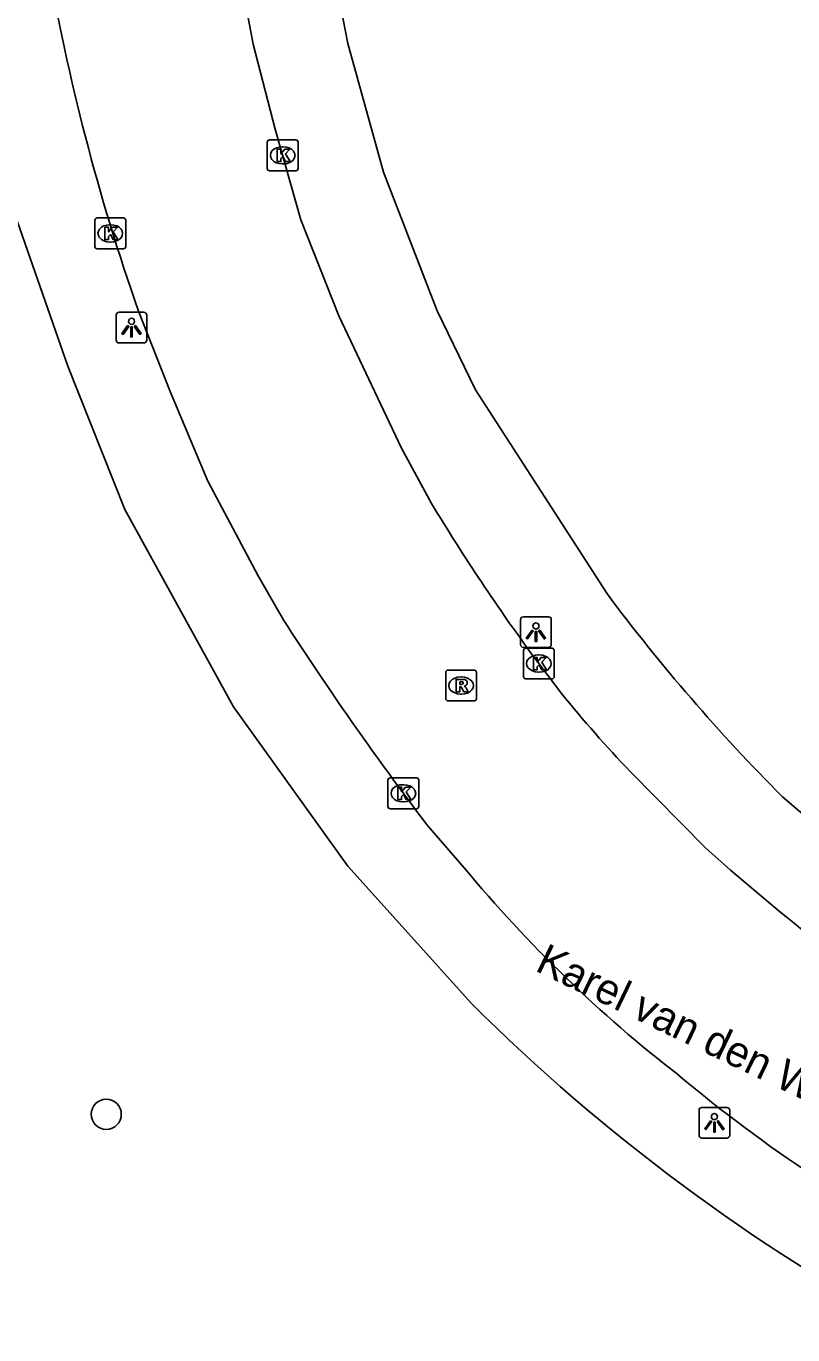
# Model space of a CAD drawing. Extents: x 161141 to 161601, y 381708 to 382245.
# Drawn here: x 161258.19 to 161283.09, y 381879.7 to 381922.19 of the extents above; entities that cross this region are included whole.
import ezdxf

# ---------------------------------------------------------------- set-up
doc = ezdxf.new("R2010")
doc.units = 0
for name, color, linetype in [('IMGEO_Boom', 7, 'Continuous'), ('IMGEO_Kolk', 7, 'Continuous'), ('IMGEO_Lichtpunt', 7, 'Continuous'), ('IMGEO_Openbare_ruimte_label', 7, 'Continuous'), ('IMGEO_Rijbaan_lokaal_open', 7, 'Continuous'), ('IMGEO_Rioolput', 7, 'Continuous'), ('IMGEO_Voetpad_open', 7, 'Continuous')]:
    doc.layers.add(name, color=color, linetype=linetype)

msp = doc.modelspace()

# ---------------------------------------------------------------- linework, layer by layer
at = {"layer": 'IMGEO_Boom'}
msp.add_circle((161260.788, 381886.858), 0.489, dxfattribs=at)
at = {"layer": 'IMGEO_Kolk'}
for p, q in [((161266.018, 381917.569), (161266.018, 381918.421)), ((161266.093, 381918.495), (161266.945, 381918.495)), ((161267.019, 381918.421), (161267.019, 381917.569)), ((161266.506, 381918.275), (161266.531, 381918.275)), ((161266.529, 381917.715), (161266.504, 381917.715)), ((161266.945, 381917.495), (161266.093, 381917.495)), ((161260.418, 381915.035), (161260.418, 381915.887)), ((161260.493, 381915.961), (161261.345, 381915.961)), ((161261.419, 381915.887), (161261.419, 381915.035)), ((161260.906, 381915.741), (161260.931, 381915.741)), ((161260.929, 381915.181), (161260.904, 381915.181)), ((161261.345, 381914.961), (161260.493, 381914.961)), ((161274.34, 381901.067), (161274.34, 381901.919)), ((161274.415, 381901.993), (161275.267, 381901.993)), ((161275.341, 381901.919), (161275.341, 381901.067)), ((161274.828, 381901.773), (161274.853, 381901.773)), ((161274.851, 381901.213), (161274.826, 381901.213)), ((161275.267, 381900.993), (161274.415, 381900.993)), ((161269.938, 381896.854), (161269.938, 381897.706)), ((161270.013, 381897.78), (161270.865, 381897.78)), ((161270.939, 381897.706), (161270.939, 381896.854)), ((161270.426, 381897.56), (161270.451, 381897.56)), ((161270.865, 381896.78), (161270.013, 381896.78)), ((161270.449, 381897), (161270.424, 381897))]:
    msp.add_line(p, q, dxfattribs=at)
for points in [[(161266.018, 381917.569), (161266.018, 381918.421)], [(161266.093, 381918.495), (161266.945, 381918.495)], [(161267.019, 381918.421), (161267.019, 381917.569)], [(161266.339, 381918.195), (161266.462, 381918.195), (161266.462, 381918.044), (161266.592, 381918.195), (161266.756, 381918.195), (161266.61, 381918.044), (161266.763, 381917.795), (161266.611, 381917.795), (161266.526, 381917.959), (161266.462, 381917.892), (161266.462, 381917.795), (161266.339, 381917.795), (161266.339, 381918.195)], [(161266.945, 381917.495), (161266.093, 381917.495)], [(161260.418, 381915.035), (161260.418, 381915.887)], [(161260.493, 381915.961), (161261.345, 381915.961)], [(161261.419, 381915.887), (161261.419, 381915.035)], [(161260.739, 381915.661), (161260.862, 381915.661), (161260.862, 381915.51), (161260.992, 381915.661), (161261.156, 381915.661), (161261.01, 381915.51), (161261.163, 381915.261), (161261.011, 381915.261), (161260.926, 381915.425), (161260.862, 381915.358), (161260.862, 381915.261), (161260.739, 381915.261), (161260.739, 381915.661)], [(161261.345, 381914.961), (161260.493, 381914.961)], [(161274.34, 381901.067), (161274.34, 381901.919)], [(161274.415, 381901.993), (161275.267, 381901.993)], [(161275.341, 381901.919), (161275.341, 381901.067)], [(161274.661, 381901.693), (161274.784, 381901.693), (161274.784, 381901.542), (161274.914, 381901.693), (161275.078, 381901.693), (161274.932, 381901.542), (161275.085, 381901.293), (161274.933, 381901.293), (161274.848, 381901.457), (161274.784, 381901.39), (161274.784, 381901.293), (161274.661, 381901.293), (161274.661, 381901.693)], [(161275.267, 381900.993), (161274.415, 381900.993)], [(161269.938, 381896.854), (161269.938, 381897.706)], [(161270.013, 381897.78), (161270.865, 381897.78)], [(161270.939, 381897.706), (161270.939, 381896.854)], [(161270.259, 381897.48), (161270.382, 381897.48), (161270.382, 381897.329), (161270.512, 381897.48), (161270.676, 381897.48), (161270.53, 381897.329), (161270.683, 381897.08), (161270.531, 381897.08), (161270.446, 381897.244), (161270.382, 381897.177), (161270.382, 381897.08), (161270.259, 381897.08), (161270.259, 381897.48)], [(161270.865, 381896.78), (161270.013, 381896.78)]]:
    msp.add_lwpolyline(points, dxfattribs=at)
for centre, start, end in [((161266.095, 381918.419), 91.552, 178.448), ((161266.095, 381918.419), 91.552, 178.448), ((161266.943, 381918.419), 1.552, 88.448), ((161266.943, 381918.419), 1.552, 88.448), ((161266.095, 381917.571), 181.552, 268.448), ((161266.095, 381917.571), 181.552, 268.448), ((161266.943, 381917.571), 271.552, 358.448), ((161266.943, 381917.571), 271.552, 358.448), ((161260.495, 381915.885), 91.552, 178.448), ((161260.495, 381915.885), 91.552, 178.448), ((161261.343, 381915.885), 1.552, 88.448), ((161261.343, 381915.885), 1.552, 88.448), ((161260.495, 381915.037), 181.552, 268.448), ((161260.495, 381915.037), 181.552, 268.448), ((161261.343, 381915.037), 271.552, 358.448), ((161261.343, 381915.037), 271.552, 358.448), ((161274.417, 381901.917), 91.552, 178.448), ((161274.417, 381901.917), 91.552, 178.448), ((161275.265, 381901.917), 1.552, 88.448), ((161275.265, 381901.917), 1.552, 88.448), ((161274.417, 381901.069), 181.552, 268.448), ((161274.417, 381901.069), 181.552, 268.448), ((161275.265, 381901.069), 271.552, 358.448), ((161275.265, 381901.069), 271.552, 358.448), ((161270.015, 381897.704), 91.552, 178.448), ((161270.015, 381897.704), 91.552, 178.448), ((161270.863, 381897.704), 1.552, 88.448), ((161270.863, 381897.704), 1.552, 88.448), ((161270.015, 381896.856), 181.552, 268.448), ((161270.015, 381896.856), 181.552, 268.448), ((161270.863, 381896.856), 271.552, 358.448), ((161270.863, 381896.856), 271.552, 358.448)]:
    msp.add_arc(centre, 0.0765, start, end, dxfattribs=at)
for centre, major_axis, ratio, start_param, end_param in [((161266.505, 381917.995), (-0.387, 0.002), 0.722429, 4.712389, 7.853982), ((161266.53, 381917.995), (-0.39, 0.002), 0.717154, 1.570796, 4.712389), ((161260.905, 381915.461), (-0.387, 0.002), 0.722429, 4.712389, 7.853982), ((161260.93, 381915.461), (-0.39, 0.002), 0.717154, 1.570796, 4.712389), ((161274.827, 381901.493), (-0.387, 0.002), 0.722429, 4.712389, 7.853982), ((161274.852, 381901.493), (-0.39, 0.002), 0.717154, 1.570796, 4.712389), ((161270.425, 381897.28), (-0.387, 0.002), 0.722429, 4.712389, 7.853982), ((161270.45, 381897.28), (-0.39, 0.002), 0.717154, 1.570796, 4.712389)]:
    msp.add_ellipse(centre, major_axis=major_axis, ratio=ratio, start_param=start_param, end_param=end_param, dxfattribs=at)
at = {"layer": 'IMGEO_Lichtpunt'}
for p, q in [((161262.011, 381912.901), (161261.203, 381912.901)), ((161262.011, 381912.901), (161261.203, 381912.901)), ((161261.109, 381912.806), (161261.109, 381911.999)), ((161261.109, 381912.806), (161261.109, 381911.999)), ((161262.105, 381911.999), (161262.105, 381912.806)), ((161262.105, 381911.999), (161262.105, 381912.806)), ((161261.203, 381911.905), (161262.011, 381911.905)), ((161261.203, 381911.905), (161262.011, 381911.905)), ((161274.246, 381902.917), (161274.246, 381902.11)), ((161274.246, 381902.917), (161274.246, 381902.11)), ((161275.148, 381903.012), (161274.34, 381903.012)), ((161275.148, 381903.012), (161274.34, 381903.012)), ((161275.242, 381902.11), (161275.242, 381902.917)), ((161275.242, 381902.11), (161275.242, 381902.917)), ((161274.34, 381902.016), (161275.148, 381902.016)), ((161274.34, 381902.016), (161275.148, 381902.016)), ((161280.043, 381886.985), (161280.043, 381886.178)), ((161280.043, 381886.985), (161280.043, 381886.178)), ((161280.945, 381887.08), (161280.137, 381887.08)), ((161280.945, 381887.08), (161280.137, 381887.08)), ((161281.039, 381886.178), (161281.039, 381886.985)), ((161281.039, 381886.178), (161281.039, 381886.985)), ((161280.137, 381886.084), (161280.945, 381886.084)), ((161280.137, 381886.084), (161280.945, 381886.084))]:
    msp.add_line(p, q, dxfattribs=at)
for points in [[(161261.483, 381912.47), (161261.522, 381912.442), (161261.334, 381912.18), (161261.296, 381912.207), (161261.483, 381912.47)], [(161261.585, 381912.422), (161261.632, 381912.422), (161261.632, 381912.1), (161261.585, 381912.1), (161261.585, 381912.422)], [(161261.695, 381912.442), (161261.733, 381912.469), (161261.92, 381912.207), (161261.881, 381912.179), (161261.695, 381912.442)], [(161274.62, 381902.581), (161274.659, 381902.553), (161274.471, 381902.291), (161274.433, 381902.318), (161274.62, 381902.581)], [(161274.722, 381902.533), (161274.769, 381902.533), (161274.769, 381902.211), (161274.722, 381902.211), (161274.722, 381902.533)], [(161274.832, 381902.553), (161274.87, 381902.58), (161275.057, 381902.318), (161275.018, 381902.29), (161274.832, 381902.553)], [(161280.417, 381886.649), (161280.456, 381886.621), (161280.268, 381886.359), (161280.23, 381886.386), (161280.417, 381886.649)], [(161280.519, 381886.601), (161280.566, 381886.601), (161280.566, 381886.279), (161280.519, 381886.279), (161280.519, 381886.601)], [(161280.629, 381886.621), (161280.667, 381886.648), (161280.854, 381886.386), (161280.815, 381886.358), (161280.629, 381886.621)]]:
    msp.add_lwpolyline(points, dxfattribs=at)
for centre in [(161261.608, 381912.604), (161274.745, 381902.715), (161280.542, 381886.783)]:
    msp.add_circle(centre, 0.0994, dxfattribs=at)
for centre, start, end in [((161261.203, 381912.806), 90, 180), ((161261.203, 381912.806), 90, 180), ((161262.011, 381912.806), 0, 90), ((161262.011, 381912.806), 0, 90), ((161261.203, 381911.999), 180, 270), ((161261.203, 381911.999), 180, 270), ((161262.011, 381911.999), 270, 0), ((161262.011, 381911.999), 270, 360), ((161274.34, 381902.917), 90, 180), ((161274.34, 381902.917), 90, 180), ((161275.148, 381902.917), 0, 90), ((161275.148, 381902.917), 0, 90), ((161274.34, 381902.11), 180, 270), ((161274.34, 381902.11), 180, 270), ((161275.148, 381902.11), 270, 0), ((161275.148, 381902.11), 270, 360), ((161280.137, 381886.985), 90, 180), ((161280.137, 381886.985), 90, 180), ((161280.945, 381886.985), 0, 90), ((161280.945, 381886.985), 0, 90), ((161280.137, 381886.178), 180, 270), ((161280.137, 381886.178), 180, 270), ((161280.945, 381886.178), 270, 0), ((161280.945, 381886.178), 270, 360)]:
    msp.add_arc(centre, 0.0946, start, end, dxfattribs=at)
at = {"layer": 'IMGEO_Rijbaan_lokaal_open'}
for points in [[(161273.208, 381990.334), (161273.075, 381989.612), (161271.16, 381978.342), (161270.456, 381974.554), (161269.186, 381967.075), (161268.219, 381960.609), (161267.185, 381954.246), (161266.311, 381948.744), (161265.934, 381946.371), (161265.288, 381942.157), (161264.932, 381939.304), (161264.554, 381936.602), (161264.405, 381933.991), (161264.331, 381930.62), (161264.526, 381927.722), (161265, 381924.596), (161265.564, 381921.601), (161266.277, 381918.847), (161267.11, 381915.904), (161268.344, 381912.783), (161270.379, 381908.492), (161271.356, 381906.689)], [(161261.835, 381912.934), (161262.866, 381910.322), (161264.089, 381907.412), (161265.722, 381904.345), (161266.554, 381902.888)], [(161274.707, 381901.67), (161275.576, 381900.526)], [(161277.808, 381897.987), (161280.259, 381895.503)], [(161270.816, 381896.775), (161271.228, 381896.235), (161272.414, 381894.865)]]:
    msp.add_lwpolyline(points, dxfattribs=at)
for centre, radius, start, end in [((161329.155, 381936.504), 71.327, 189.79024, 199.2957), ((161327.716, 381940.691), 65.822, 211.10209, 216.35704), ((161357.146, 381961.507), 107.903, 212.90543, 216.8632), ((161305.516, 381924.595), 38.415, 218.7964, 223.8402), ((161326.411, 381946.909), 69.084, 228.08278, 235.22747), ((161306.253, 381922.87), 43.924, 219.6115, 232.2855), ((161311.453, 381926.489), 50.005, 230.1076, 242.7376)]:
    msp.add_arc(centre, radius, start, end, dxfattribs=at)
at = {"layer": 'IMGEO_Rioolput'}
for p, q in [((161271.813, 381900.354), (161271.813, 381901.206)), ((161271.888, 381901.28), (161272.74, 381901.28)), ((161272.301, 381901.06), (161272.326, 381901.06)), ((161272.814, 381901.206), (161272.814, 381900.354)), ((161272.74, 381900.28), (161271.888, 381900.28)), ((161272.324, 381900.5), (161272.299, 381900.5))]:
    msp.add_line(p, q, dxfattribs=at)
for points in [[(161271.813, 381900.354), (161271.813, 381901.206)], [(161271.888, 381901.28), (161272.74, 381901.28)], [(161272.814, 381901.206), (161272.814, 381900.354)], [(161272.402, 381900.978), (161272.15, 381900.98), (161272.15, 381900.58)], [(161272.15, 381900.58), (161272.274, 381900.58), (161272.274, 381900.742), (161272.285, 381900.742)], [(161272.328, 381900.899), (161272.274, 381900.899), (161272.274, 381900.818)], [(161272.274, 381900.818), (161272.326, 381900.818)], [(161272.332, 381900.713), (161272.403, 381900.58), (161272.543, 381900.58), (161272.478, 381900.706)], [(161272.74, 381900.28), (161271.888, 381900.28)]]:
    msp.add_lwpolyline(points, dxfattribs=at)
for centre, radius, start, end in [((161271.89, 381901.204), 0.0765, 91.552, 178.448), ((161271.89, 381901.204), 0.0765, 91.552, 178.448), ((161272.738, 381901.204), 0.0765, 1.552, 88.448), ((161272.738, 381901.204), 0.0765, 1.552, 88.448), ((161272.284, 381900.689), 0.0533, 26.0293, 88.6989), ((161272.31, 381901.007), 0.19, 274.7715, 282.9687), ((161272.334, 381900.803), 0.0964, 77.0061, 93.1865), ((161272.348, 381900.86), 0.0378, 276.6634, 79.6772), ((161272.401, 381900.868), 0.109, 350.3612, 89.416), ((161272.399, 381900.868), 0.112, 277.5842, 350.9817), ((161272.383, 381900.653), 0.108, 29.5134, 73.7905), ((161271.89, 381900.356), 0.0765, 181.552, 268.448), ((161271.89, 381900.356), 0.0765, 181.552, 268.448), ((161272.738, 381900.356), 0.0765, 271.552, 358.448), ((161272.738, 381900.356), 0.0765, 271.552, 358.448)]:
    msp.add_arc(centre, radius, start, end, dxfattribs=at)
for centre, major_axis, ratio, start_param, end_param in [((161272.3, 381900.78), (-0.387, 0.002), 0.722429, 4.712389, 7.853982), ((161272.325, 381900.78), (-0.39, 0.002), 0.717154, 1.570796, 4.712389)]:
    msp.add_ellipse(centre, major_axis=major_axis, ratio=ratio, start_param=start_param, end_param=end_param, dxfattribs=at)
at = {"layer": 'IMGEO_Voetpad_open'}
for points in [[(161276.309, 381989.126), (161276.14, 381989.025), (161267.873, 381937.797), (161267.435, 381933.784), (161267.467, 381929.855), (161267.871, 381925.589), (161268.634, 381921.624), (161269.796, 381917.444), (161271.533, 381912.948), (161272.783, 381910.378), (161277.045, 381903.774)], [(161272.651, 381890.451), (161268.63, 381894.919), (161264.924, 381900.093), (161261.387, 381906.491), (161259.539, 381911.147), (161257.417, 381917.229)], [(161282.757, 381897.162), (161285.416, 381894.897), (161286.952, 381893.797), (161293.664, 381889.876), (161297.982, 381887.859), (161317.522, 381879.697)]]:
    msp.add_lwpolyline(points, dxfattribs=at)
for centre, radius, start, end in [((161325.918, 381940.222), 60.967, 216.71398, 224.93243), ((161316.981, 381935.088), 62.91, 225.19754, 241.65079)]:
    msp.add_arc(centre, radius, start, end, dxfattribs=at)

# ---------------------------------------------------------------- texts
at = {"layer": 'IMGEO_Openbare_ruimte_label'}
msp.add_text('Karel van den Woestijnelaan', height=1, rotation=334.2805, dxfattribs=at).set_placement((161274.682, 381891.533))

doc.saveas('drawing.dxf')
